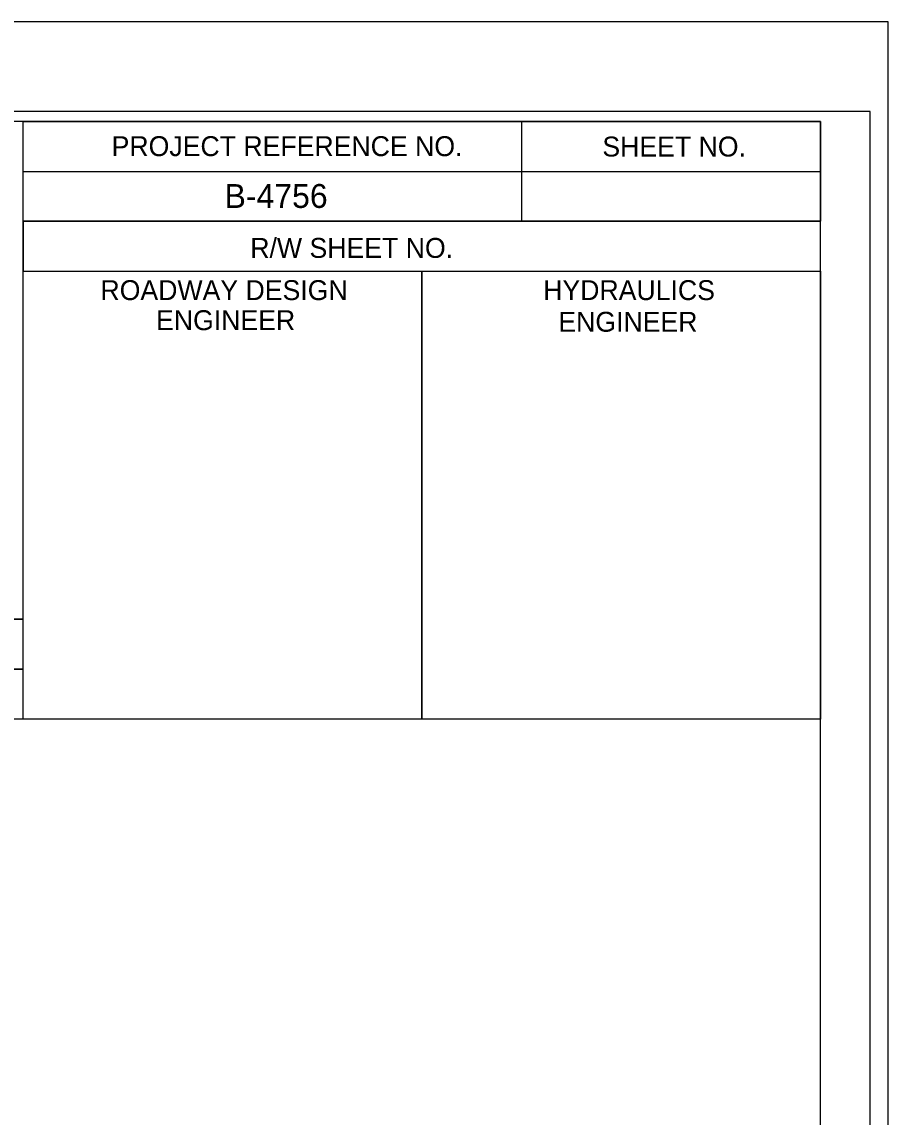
# Model space of a CAD drawing. Extents: x 2431000 to 2534000, y 645879 to 714000.
# Drawn here: x 2465318.8 to 2465536.2, y 672203.6 to 672478.6 of the extents above; entities that cross this region are included whole.
import ezdxf

# ---------------------------------------------------------------- set-up
doc = ezdxf.new("R2010")
doc.units = 0
for name, color, linetype in [('KHA_LOGO', 7, 'Continuous'), ('Prop Dimension', 7, 'Continuous'), ('Prop Terminator CELL', 7, 'Continuous'), ('Sheet Clip Boundary CELL', 7, 'Continuous')]:
    doc.layers.add(name, color=color, linetype=linetype)

msp = doc.modelspace()

# ---------------------------------------------------------------- linework, layer by layer
at = {"layer": 'KHA_LOGO'}
for p, q in [((2465444.2, 672453.58), (2465444.2, 672428.58)), ((2465319.15, 672441.08), (2465519.2, 672441.08)), ((2465319.15, 672428.58), (2465519.2, 672428.58)), ((2465319.15, 672428.58), (2465319.15, 672416.08)), ((2465319.15, 672428.58), (2465519.2, 672428.58)), ((2465419.2, 672416.08), (2465419.2, 672303.63))]:
    msp.add_line(p, q, dxfattribs=at)
for points in [[(2465519.2, 672453.63), (2464019.2, 672453.63), (2464019.2, 671403.63), (2465519.2, 671403.63)], [(2465319.15, 672453.63), (2465519.2, 672453.63), (2465519.2, 672428.58), (2465319.15, 672428.58)], [(2465319.15, 672416.08), (2465419.2, 672416.08), (2465419.2, 672303.58), (2465319.15, 672303.58)], [(2465419.2, 672416.08), (2465519.2, 672416.08), (2465519.2, 672303.58), (2465419.2, 672303.58)]]:
    msp.add_lwpolyline(points, close=True, dxfattribs=at)
at = {"layer": 'Prop Dimension'}
msp.add_lwpolyline([(2463852.7, 671378.63), (2465536.2, 671378.63), (2465536.2, 672478.63), (2463852.7, 672478.63)], close=True, dxfattribs=at)
at = {"layer": 'Prop Terminator CELL'}
msp.add_lwpolyline([(2463865.7, 671401.13), (2465531.7, 671401.13), (2465531.7, 672456.13), (2463865.7, 672456.13)], close=True, dxfattribs=at)
at = {"layer": 'Sheet Clip Boundary CELL'}
for points in [[(2465219.15, 672328.63), (2465319.15, 672328.63), (2465319.15, 672453.63), (2465219.15, 672453.63)], [(2465219.15, 672316.13), (2465319.15, 672316.13), (2465319.15, 672328.63), (2465219.15, 672328.63)], [(2465219.15, 672303.63), (2465319.15, 672303.63), (2465319.15, 672316.13), (2465219.15, 672316.13)]]:
    msp.add_lwpolyline(points, close=True, dxfattribs=at)

# ---------------------------------------------------------------- texts
at = {"layer": 'KHA_LOGO'}
for s, height, p in [('PROJECT REFERENCE NO.', 5.0001, (2465341.35, 672444.93)), ('SHEET NO.', 5, (2465464.5, 672444.83)), ('B-4756', 6, (2465369.69, 672431.92)), ('R/W SHEET NO.', 5.0001, (2465376.15, 672419.38)), ('ROADWAY DESIGN', 5.0001, (2465338.55, 672408.78)), ('HYDRAULICS', 5, (2465449.65, 672408.78)), ('ENGINEER', 5, (2465352.5, 672401.23)), ('ENGINEER', 5, (2465453.45, 672400.83))]:
    msp.add_text(s, height=height, dxfattribs=at).set_placement(p)

doc.saveas('drawing.dxf')
